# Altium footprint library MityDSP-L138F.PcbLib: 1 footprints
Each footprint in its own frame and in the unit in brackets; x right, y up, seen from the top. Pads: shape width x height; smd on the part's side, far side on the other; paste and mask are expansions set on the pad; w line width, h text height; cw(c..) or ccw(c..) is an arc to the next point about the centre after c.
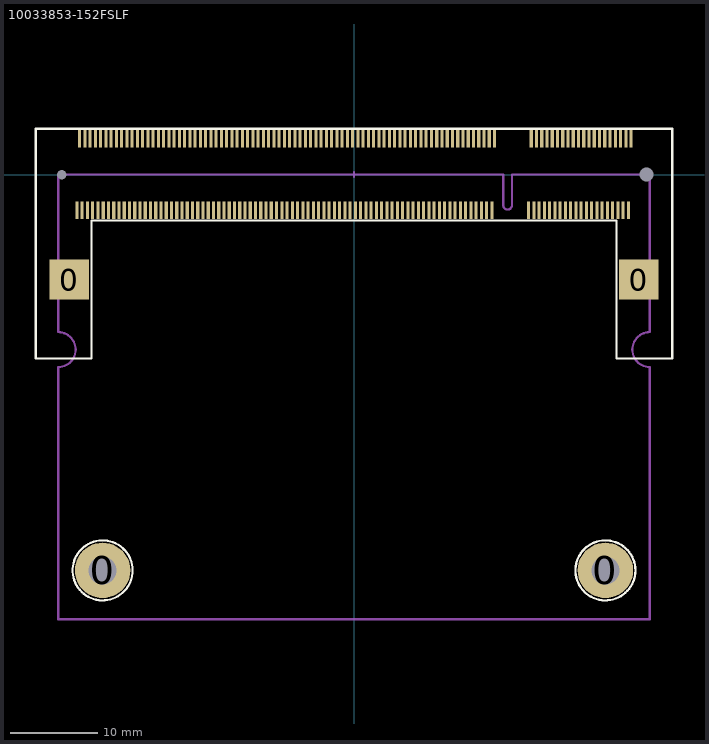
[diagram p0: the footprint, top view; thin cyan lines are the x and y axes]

## 10033853-152FSLF [mm] "CONN SODIMM DDR2 200POS R/A SMD"
height 1.9
pads (206):
  round 0 hole 1.1 unplated: 0(-33.4,0)
  rect 4.5x4.6 smd: 0(-32.55,-12) 0(32.55,-12)
  round 6.35 hole 3.175: 0(-28.72,-45.22) 0(28.72,-45.22)
  round 0 hole 1.6 unplated: 0(33.4,0)
  rect 0.35x2 smd: 1(31.65,4.1) 2(31.35,-4.1) 3(31.05,4.1) 4(30.75,-4.1) 5(30.45,4.1) 6(30.15,-4.1) 7(29.85,4.1) 8(29.55,-4.1) 9(29.25,4.1) 10(28.95,-4.1) 11(28.65,4.1) 12(28.35,-4.1) 13(28.05,4.1) 14(27.75,-4.1) 15(27.45,4.1) 16(27.15,-4.1) 17(26.85,4.1) 18(26.55,-4.1) 19(26.25,4.1) 20(25.95,-4.1) 21(25.65,4.1) 22(25.35,-4.1) 23(25.05,4.1) 24(24.75,-4.1) 25(24.45,4.1) 26(24.15,-4.1) 27(23.85,4.1) 28(23.55,-4.1) 29(23.25,4.1) 30(22.95,-4.1) 31(22.65,4.1) 32(22.35,-4.1) 33(22.05,4.1) 34(21.75,-4.1) 35(21.45,4.1) 36(21.15,-4.1) 37(20.85,4.1) 38(20.55,-4.1) 39(20.25,4.1) 40(19.95,-4.1) 41(16.05,4.1) 42(15.75,-4.1) 43(15.45,4.1) 44(15.15,-4.1) 45(14.85,4.1) 46(14.55,-4.1) 47(14.25,4.1) 48(13.95,-4.1) 49(13.65,4.1) 50(13.35,-4.1) 51(13.05,4.1) 52(12.75,-4.1) 53(12.45,4.1) 54(12.15,-4.1) 55(11.85,4.1) 56(11.55,-4.1) 57(11.25,4.1) 58(10.95,-4.1) 59(10.65,4.1) 60(10.35,-4.1) 61(10.05,4.1) 62(9.75,-4.1) 63(9.45,4.1) 64(9.15,-4.1) 65(8.85,4.1) 66(8.55,-4.1) 67(8.25,4.1) 68(7.95,-4.1) 69(7.65,4.1) 70(7.35,-4.1) 71(7.05,4.1) 72(6.75,-4.1) 73(6.45,4.1) 74(6.15,-4.1) 75(5.85,4.1) 76(5.55,-4.1) 77(5.25,4.1) 78(4.95,-4.1) 79(4.65,4.1) 80(4.35,-4.1) 81(4.05,4.1) 82(3.75,-4.1) 83(3.45,4.1) 84(3.15,-4.1) 85(2.85,4.1) 86(2.55,-4.1) 87(2.25,4.1) 88(1.95,-4.1) 89(1.65,4.1) 90(1.35,-4.1) 91(1.05,4.1) 92(0.75,-4.1) 93(0.45,4.1) 94(0.15,-4.1) 95(-0.15,4.1) 96(-0.45,-4.1) 97(-0.75,4.1) 98(-1.05,-4.1) 99(-1.35,4.1) 100(-1.65,-4.1) 101(-1.95,4.1) 102(-2.25,-4.1) 103(-2.55,4.1) 104(-2.85,-4.1) 105(-3.15,4.1) 106(-3.45,-4.1) 107(-3.75,4.1) 108(-4.05,-4.1) 109(-4.35,4.1) 110(-4.65,-4.1) 111(-4.95,4.1) 112(-5.25,-4.1) 113(-5.55,4.1) 114(-5.85,-4.1) 115(-6.15,4.1) 116(-6.45,-4.1) 117(-6.75,4.1) 118(-7.05,-4.1) 119(-7.35,4.1) 120(-7.65,-4.1) 121(-7.95,4.1) 122(-8.25,-4.1) 123(-8.55,4.1) 124(-8.85,-4.1) 125(-9.15,4.1) 126(-9.45,-4.1) 127(-9.75,4.1) 128(-10.05,-4.1) 129(-10.35,4.1) 130(-10.65,-4.1) 131(-10.95,4.1) 132(-11.25,-4.1) 133(-11.55,4.1) 134(-11.85,-4.1) 135(-12.15,4.1) 136(-12.45,-4.1) 137(-12.75,4.1) 138(-13.05,-4.1) 139(-13.35,4.1) 140(-13.65,-4.1) 141(-13.95,4.1) 142(-14.25,-4.1) 143(-14.55,4.1) 144(-14.85,-4.1) 145(-15.15,4.1) 146(-15.45,-4.1) 147(-15.75,4.1) 148(-16.05,-4.1) 149(-16.35,4.1) 150(-16.65,-4.1) 151(-16.95,4.1) 152(-17.25,-4.1) 153(-17.55,4.1) 154(-17.85,-4.1) 155(-18.15,4.1) 156(-18.45,-4.1) 157(-18.75,4.1) 158(-19.05,-4.1) 159(-19.35,4.1) 160(-19.65,-4.1) 161(-19.95,4.1) 162(-20.25,-4.1) 163(-20.55,4.1) 164(-20.85,-4.1) 165(-21.15,4.1) 166(-21.45,-4.1) 167(-21.75,4.1) 168(-22.05,-4.1) 169(-22.35,4.1) 170(-22.65,-4.1) 171(-22.95,4.1) 172(-23.25,-4.1) 173(-23.55,4.1) 174(-23.85,-4.1) 175(-24.15,4.1) 176(-24.45,-4.1) 177(-24.75,4.1) 178(-25.05,-4.1) 179(-25.35,4.1) 180(-25.65,-4.1) 181(-25.95,4.1) 182(-26.25,-4.1) 183(-26.55,4.1) 184(-26.85,-4.1) 185(-27.15,4.1) 186(-27.45,-4.1) 187(-27.75,4.1) 188(-28.05,-4.1) 189(-28.35,4.1) 190(-28.65,-4.1) 191(-28.95,4.1) 192(-29.25,-4.1) 193(-29.55,4.1) 194(-29.85,-4.1) 195(-30.15,4.1) 196(-30.45,-4.1) 197(-30.75,4.1) 198(-31.05,-4.1) 199(-31.35,4.1) 200(-31.65,-4.1)
Top Overlay:
  circle w0.254: c-28.72,-45.22 r3.429
  circle w0.254: c28.72,-45.22 r3.429
  lines w0.254: -36.35,-21 -36.35,5.232 36.35,5.232 36.35,-21 30,-21 30,-5.258 -30,-5.258 -30,-21 -36.35,-21
Mechanical 1:
  lines w0.254: -0.254,0 0.254,0 ; 0,-0.254 0,0.254 ; 17.05,-3.5 ccw(c17.55,-3.5) 18.05,-3.5 18.05,0 33.8,0 33.8,-18 ccw(c33.8,-20) 33.8,-22 33.8,-50.8 -33.8,-50.8 -33.8,-22 ccw(c-33.8,-20) -33.8,-18 -33.8,0 17.05,0 17.05,-3.5
  text "MityOMAP outline" at -7.874,-49.022 h1.27
  text "Keep-Out for High Profile components" at -21.59,-19.431 h1.27
Mechanical 3:
  lines w0.254: -33.8,-38.1 -33.8,-22 ; 33.8,-38.1 33.8,-22
3D body: height 5.1, standoff -0.8, extent -35.998,-20.069 36.302,5.131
